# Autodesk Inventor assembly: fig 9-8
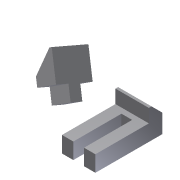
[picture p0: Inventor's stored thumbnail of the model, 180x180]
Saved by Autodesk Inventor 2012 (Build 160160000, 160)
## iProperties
Shininess: 64.0
Length Units: 11269
Angle Units: 11279
Time Units: 11290
Mass Units: 11283
Length Display Precision: 3
Angle Display Precision: 2
Created: 2002-01
Part Number: fig 9-8
Document SubType Name: Assembly
Designer: ***
Density: 0.0
Volumn: 0.0
Area: 0.0
PropertySet Name: Model Information
Control State: 0
Master: False
Checked Out: False
Author: ***
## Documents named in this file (3)
- C:\Users\CadCim\Documents\SAILESH\inventor-2011-fact-prt\c09-inv-2011-prt\c09_inv_2012_prt\fig 9-8.iam
- C:\Users\CadCim\Documents\SAILESH\inventor-2011-fact-prt\c09-inv-2011-prt\c09_inv_2012_prt\fig 9-8\Part3.ipt
- C:\Users\CadCim\Documents\SAILESH\inventor-2011-fact-prt\c09-inv-2011-prt\c09_inv_2012_prt\fig 9-8\Part4.ipt
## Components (2 placed, 2 different names)
1. Part3:1
2. Part4:1
